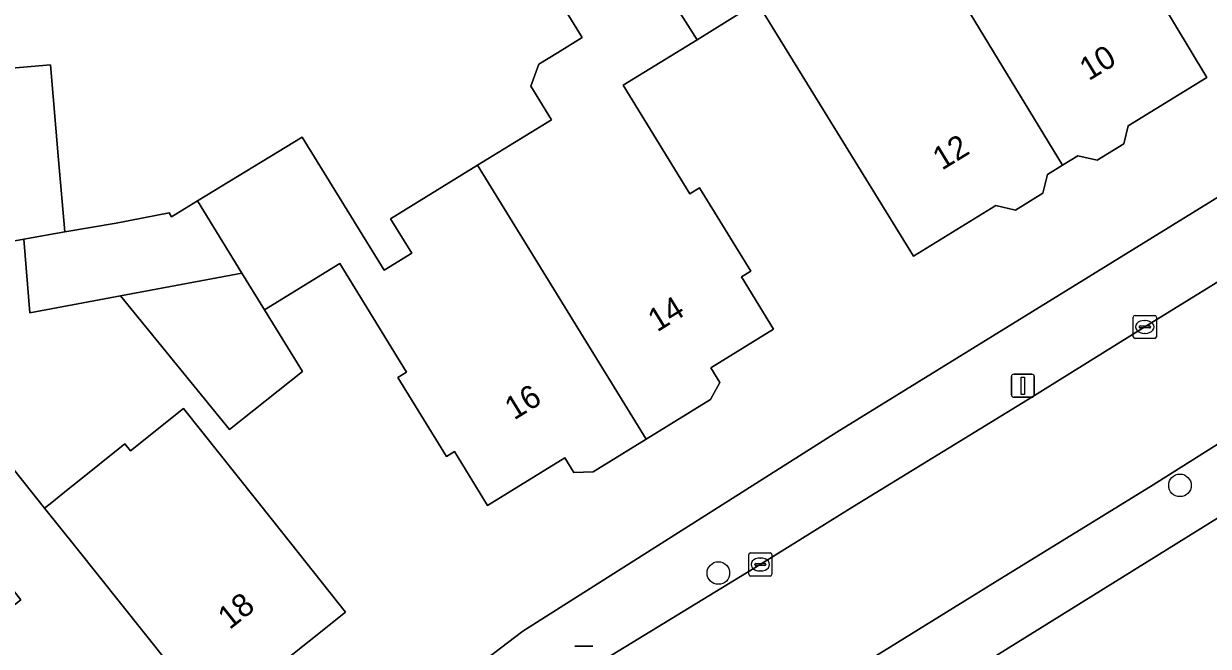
# Model space of a CAD drawing. Extents: x 161347 to 161881, y 382161 to 382804.
# Drawn here: x 161497.7 to 161549.1, y 382335.1 to 382362.1 of the extents above; entities that cross this region are included whole.
import ezdxf

# ---------------------------------------------------------------- set-up
doc = ezdxf.new("R2010")
doc.units = 0
for name, color, linetype in [('IMGEO_Boom', 7, 'Continuous'), ('IMGEO_Erf', 7, 'Continuous'), ('IMGEO_Kolk', 7, 'Continuous'), ('IMGEO_Lichtmast', 7, 'Continuous'), ('IMGEO_Pand', 7, 'Continuous'), ('IMGEO_Pand_nummerreeks', 7, 'Continuous'), ('IMGEO_Rijbaan_lokaal_open', 7, 'Continuous'), ('IMGEO_Voetpad_open', 7, 'Continuous')]:
    doc.layers.add(name, color=color, linetype=linetype)

msp = doc.modelspace()

# ---------------------------------------------------------------- linework, layer by layer
at = {"layer": 'IMGEO_Boom'}
for centre in [(161547.837, 382342.1), (161527.839, 382338.303)]:
    msp.add_circle(centre, 0.489, dxfattribs=at)
at = {"layer": 'IMGEO_Erf'}
for points in [[(161492.761, 382318.284), (161495.67, 382317.265), (161500, 382320.746), (161506.91, 382326.302), (161519.365, 382335.787), (161532.97, 382344.41), (161567.929, 382365.979), (161578.374, 382372.283), (161617.144, 382396.335)], [(161622.482, 382385.769), (161592.982, 382367.466), (161570.924, 382353.999), (161525.486, 382325.795), (161515.87, 382318.353), (161502.943, 382308.001)], [(161541.411, 382372.389), (161548.998, 382359.767), (161545.591, 382357.669), (161545.408, 382356.898), (161544.243, 382356.181), (161543.409, 382356.379), (161542.751, 382355.974), (161542.092, 382355.568), (161541.897, 382354.749), (161540.709, 382354.017), (161539.857, 382354.22), (161536.289, 382352.023), (161529.524, 382363.007), (161526.913, 382361.399), (161523.711, 382359.427), (161526.606, 382354.727), (161527.02, 382354.982), (161529.239, 382351.379), (161528.839, 382351.133), (161530.233, 382348.869), (161527.506, 382347.19), (161527.899, 382346.551), (161527.504, 382345.82), (161524.713, 382344.101), (161522.412, 382342.684), (161521.578, 382342.66), (161521.185, 382343.298), (161517.835, 382341.235), (161516.401, 382343.565), (161516.059, 382343.354), (161513.953, 382346.775), (161514.328, 382347.006), (161511.435, 382351.707), (161508.174, 382349.7), (161509.821, 382347.027), (161506.662, 382344.526), (161501.933, 382350.307), (161498.009, 382349.575), (161497.75, 382352.769), (161497.358, 382352.698)], [(161496.711, 382360.131), (161498.911, 382360.315), (161499.257, 382356.205), (161499.52, 382353.085), (161501.753, 382353.46), (161504.044, 382353.9), (161504.147, 382353.731), (161505.273, 382354.418), (161509.811, 382357.184), (161513.362, 382351.416), (161514.557, 382352.152), (161513.638, 382353.644), (161517.407, 382355.965), (161520.609, 382357.937), (161519.714, 382359.39), (161520.065, 382360.343), (161520.868, 382360.838), (161521.941, 382361.498), (161519.162, 382366.01)]]:
    msp.add_lwpolyline(points, dxfattribs=at)
msp.add_lwpolyline([(161511.691, 382336.608), (161508.532, 382334.091), (161508.385, 382332.789), (161507.808, 382332.33), (161506.507, 382332.477), (161505.918, 382332.008), (161502.662, 382329.412), (161502.518, 382328.135), (161501.894, 382327.638), (161500.663, 382327.777), (161500, 382327.253), (161497.42, 382325.215), (161491.686, 382332.42), (161497.616, 382337.139), (161494.169, 382341.47), (161496.735, 382343.512), (161498.649, 382341.115), (161498.885, 382341.304), (161499.745, 382341.991), (161500, 382342.195), (161502.125, 382343.894), (161502.363, 382343.594), (161504.663, 382345.427), (161508.575, 382340.519)], close=True, dxfattribs=at)
at = {"layer": 'IMGEO_Kolk'}
for p, q in [((161545.89, 382349.463), (161546.742, 382349.463)), ((161545.815, 382348.537), (161545.815, 382349.389)), ((161546.074, 382348.957), (161546.074, 382348.969)), ((161546.512, 382348.92), (161546.114, 382348.92)), ((161546.117, 382349.006), (161546.515, 382349.006)), ((161546.303, 382349.243), (161546.328, 382349.243)), ((161546.558, 382348.969), (161546.558, 382348.957)), ((161546.816, 382349.389), (161546.816, 382348.537)), ((161546.742, 382348.463), (161545.89, 382348.463)), ((161546.326, 382348.683), (161546.301, 382348.683)), ((161529.231, 382339.174), (161530.083, 382339.174)), ((161529.156, 382338.248), (161529.156, 382339.1)), ((161529.415, 382338.668), (161529.415, 382338.68)), ((161529.853, 382338.631), (161529.455, 382338.631)), ((161529.458, 382338.717), (161529.856, 382338.717)), ((161529.644, 382338.954), (161529.669, 382338.954)), ((161529.899, 382338.68), (161529.899, 382338.668)), ((161530.157, 382339.1), (161530.157, 382338.248)), ((161530.083, 382338.174), (161529.231, 382338.174)), ((161529.667, 382338.394), (161529.642, 382338.394))]:
    msp.add_line(p, q, dxfattribs=at)
for points in [[(161545.89, 382349.463), (161546.742, 382349.463)], [(161545.815, 382348.537), (161545.815, 382349.389)], [(161546.816, 382349.389), (161546.816, 382348.537)], [(161546.742, 382348.463), (161545.89, 382348.463)], [(161529.231, 382339.174), (161530.083, 382339.174)], [(161529.156, 382338.248), (161529.156, 382339.1)], [(161530.157, 382339.1), (161530.157, 382338.248)], [(161530.083, 382338.174), (161529.231, 382338.174)]]:
    msp.add_lwpolyline(points, dxfattribs=at)
for centre, radius, start, end in [((161545.892, 382349.387), 0.0765, 91.552, 178.448), ((161545.892, 382349.387), 0.0765, 91.552, 178.448), ((161546.74, 382349.387), 0.0765, 1.552, 88.448), ((161546.74, 382349.387), 0.0765, 1.552, 88.448), ((161546.114, 382348.966), 0.0403, 85.8775, 175.7526), ((161546.111, 382348.956), 0.0366, 178.938, 274.7102), ((161546.515, 382348.963), 0.043, 264.8664, 352.4533), ((161546.519, 382348.968), 0.0386, 1.7309, 96.639), ((161545.892, 382348.539), 0.0765, 181.552, 268.448), ((161545.892, 382348.539), 0.0765, 181.552, 268.448), ((161546.74, 382348.539), 0.0765, 271.552, 358.448), ((161546.74, 382348.539), 0.0765, 271.552, 358.448), ((161529.233, 382339.098), 0.0765, 91.552, 178.448), ((161529.233, 382339.098), 0.0765, 91.552, 178.448), ((161530.081, 382339.098), 0.0765, 1.552, 88.448), ((161530.081, 382339.098), 0.0765, 1.552, 88.448), ((161529.455, 382338.677), 0.0403, 85.8775, 175.7526), ((161529.452, 382338.667), 0.0366, 178.938, 274.7102), ((161529.856, 382338.674), 0.043, 264.8664, 352.4533), ((161529.86, 382338.679), 0.0386, 1.7309, 96.639), ((161529.233, 382338.25), 0.0765, 181.552, 268.448), ((161529.233, 382338.25), 0.0765, 181.552, 268.448), ((161530.081, 382338.25), 0.0765, 271.552, 358.448), ((161530.081, 382338.25), 0.0765, 271.552, 358.448)]:
    msp.add_arc(centre, radius, start, end, dxfattribs=at)
for centre, major_axis, ratio, start_param, end_param in [((161546.302, 382348.963), (-0.387, 0.002), 0.722429, 4.712389, 7.853982), ((161546.327, 382348.963), (-0.39, 0.002), 0.717154, 1.570796, 4.712389), ((161529.643, 382338.674), (-0.387, 0.002), 0.722429, 4.712389, 7.853982), ((161529.668, 382338.674), (-0.39, 0.002), 0.717154, 1.570796, 4.712389)]:
    msp.add_ellipse(centre, major_axis=major_axis, ratio=ratio, start_param=start_param, end_param=end_param, dxfattribs=at)
at = {"layer": 'IMGEO_Lichtmast'}
for p, q in [((161540.634, 382346.916), (161541.424, 382346.916)), ((161541.424, 382346.916), (161540.634, 382346.916)), ((161540.534, 382346.016), (161540.534, 382346.816)), ((161540.534, 382346.816), (161540.534, 382346.016)), ((161541.524, 382346.816), (161541.524, 382346.016)), ((161541.524, 382346.016), (161541.524, 382346.816)), ((161541.424, 382345.916), (161540.634, 382345.916)), ((161540.634, 382345.916), (161541.424, 382345.916)), ((161521.613, 382335.13), (161522.403, 382335.13)), ((161522.403, 382335.13), (161521.613, 382335.13))]:
    msp.add_line(p, q, dxfattribs=at)
msp.add_lwpolyline([(161540.954, 382346.791), (161541.104, 382346.791), (161541.104, 382346.041), (161540.954, 382346.041), (161540.954, 382346.791)], dxfattribs=at)
for centre, start, end in [((161540.634, 382346.816), 90, 180), ((161540.634, 382346.816), 90, 180), ((161541.424, 382346.816), 0, 90), ((161541.424, 382346.816), 360, 90), ((161540.634, 382346.016), 180, 270), ((161540.634, 382346.016), 180, 270), ((161541.424, 382346.016), 270, 0), ((161541.424, 382346.016), 270, 0)]:
    msp.add_arc(centre, 0.1, start, end, dxfattribs=at)
at = {"layer": 'IMGEO_Pand'}
for points in [[(161536.787, 382365.679), (161537.934, 382363.884), (161542.751, 382355.974), (161543.409, 382356.379), (161544.243, 382356.181), (161545.408, 382356.898), (161545.591, 382357.669), (161548.998, 382359.767), (161541.411, 382372.389), (161543.83, 382373.843), (161542.804, 382375.51), (161539.552, 382380.789), (161535.645, 382387.132), (161535.578, 382387.241), (161532.345, 382385.251), (161540.939, 382372.189), (161538.171, 382370.485), (161540.006, 382367.505)], [(161526.913, 382361.399), (161523.396, 382366.941), (161522.21, 382368.807), (161519.162, 382366.01), (161521.941, 382361.498), (161520.868, 382360.838), (161520.065, 382360.343), (161519.714, 382359.39), (161520.609, 382357.937), (161517.407, 382355.965), (161524.713, 382344.101), (161527.504, 382345.82), (161527.899, 382346.551), (161527.506, 382347.19), (161530.233, 382348.869), (161528.839, 382351.133), (161529.239, 382351.379), (161527.02, 382354.982), (161526.606, 382354.727), (161523.711, 382359.427)], [(161536.787, 382365.679), (161533.288, 382363.694), (161531.537, 382366.537), (161528.524, 382364.681), (161526.105, 382368.609), (161523.396, 382366.941), (161526.913, 382361.399), (161529.524, 382363.007), (161536.289, 382352.023), (161539.857, 382354.22), (161540.709, 382354.017), (161541.897, 382354.749), (161542.092, 382355.568), (161542.751, 382355.974), (161537.934, 382363.884)], [(161497.75, 382352.769), (161497.752, 382352.769), (161499.52, 382353.085), (161499.257, 382356.205), (161498.911, 382360.315), (161496.711, 382360.131), (161496.653, 382360.502), (161490.935, 382360.023), (161485.952, 382359.604), (161486.037, 382358.585), (161485.408, 382357.84), (161485.507, 382356.655), (161486.255, 382356.023), (161486.61, 382351.797), (161489.441, 382352.035), (161489.468, 382351.71), (161493.453, 382352.045), (161493.425, 382352.37), (161497.358, 382352.698)], [(161505.273, 382354.418), (161507.196, 382351.29), (161508.174, 382349.7), (161511.435, 382351.707), (161514.328, 382347.006), (161513.953, 382346.775), (161516.059, 382343.354), (161516.401, 382343.565), (161517.835, 382341.235), (161521.185, 382343.298), (161521.578, 382342.66), (161522.412, 382342.684), (161524.713, 382344.101), (161517.407, 382355.965), (161513.638, 382353.644), (161514.557, 382352.152), (161513.362, 382351.416), (161509.811, 382357.184)], [(161505.273, 382354.418), (161504.147, 382353.731), (161504.044, 382353.9), (161501.753, 382353.46), (161499.52, 382353.085), (161497.752, 382352.769), (161497.75, 382352.769), (161498.009, 382349.575), (161501.933, 382350.307), (161507.196, 382351.29)], [(161508.174, 382349.7), (161507.196, 382351.29), (161501.933, 382350.307), (161506.662, 382344.526), (161509.821, 382347.027)], [(161498.649, 382341.115), (161500, 382339.422), (161505.918, 382332.008), (161506.507, 382332.477), (161507.808, 382332.33), (161508.385, 382332.789), (161508.532, 382334.091), (161511.691, 382336.608), (161508.575, 382340.519), (161504.663, 382345.427), (161502.363, 382343.594), (161502.125, 382343.894), (161500, 382342.195), (161499.745, 382341.991), (161498.885, 382341.304)], [(161498.649, 382341.115), (161496.735, 382343.512), (161494.169, 382341.47), (161497.616, 382337.139), (161491.686, 382332.42), (161497.42, 382325.215), (161500, 382327.253), (161500.663, 382327.777), (161501.894, 382327.638), (161502.518, 382328.135), (161502.662, 382329.412), (161505.918, 382332.008), (161500, 382339.422)]]:
    msp.add_lwpolyline(points, close=True, dxfattribs=at)
at = {"layer": 'IMGEO_Rijbaan_lokaal_open'}
msp.add_lwpolyline([(161527.695, 382330.423), (161533.292, 382333.868), (161540.031, 382338.038), (161546.562, 382342.054), (161553.326, 382346.303), (161550.162, 382351.34), (161546.313, 382348.96), (161541.227, 382345.802), (161533.737, 382341.207), (161529.654, 382338.671), (161522.13, 382334.077)], dxfattribs=at)
at = {"layer": 'IMGEO_Voetpad_open'}
for points in [[(161588.821, 382375.192), (161595.489, 382379.316), (161598.349, 382381.063), (161606.195, 382385.906), (161608.544, 382387.356), (161617.711, 382393.014), (161617.891, 382393.131), (161617.144, 382396.335), (161578.374, 382372.283), (161567.929, 382365.979), (161532.97, 382344.41), (161519.365, 382335.787), (161506.91, 382326.302), (161500, 382320.746), (161495.67, 382317.265), (161490.849, 382315.425), (161491.37, 382314.562)], [(161570.924, 382353.999), (161592.982, 382367.466), (161622.482, 382385.769), (161620.875, 382387.995), (161620.649, 382387.867), (161611.66, 382382.307), (161609.313, 382380.856), (161601.422, 382375.975), (161597.335, 382373.472), (161594.082, 382371.461), (161584.84, 382365.72), (161582.402, 382364.234), (161575.759, 382360.113), (161563.07, 382352.279), (161557.478, 382348.912), (161555.662, 382347.771), (161553.326, 382346.303), (161546.562, 382342.054), (161540.031, 382338.038), (161533.292, 382333.868), (161527.695, 382330.423)], [(161522.13, 382334.077), (161529.654, 382338.671), (161533.737, 382341.207), (161541.227, 382345.802), (161546.313, 382348.96), (161550.162, 382351.34), (161552.057, 382352.512), (161552.51, 382352.791), (161558.736, 382356.63), (161563.81, 382359.731), (161570.286, 382363.724), (161577.21, 382368.009), (161581.313, 382370.53), (161588.821, 382375.192)], [(161498.134, 382305.394), (161498.735, 382304.575), (161502.943, 382308.001), (161515.87, 382318.353), (161525.486, 382325.795), (161570.924, 382353.999)]]:
    msp.add_lwpolyline(points, dxfattribs=at)

# ---------------------------------------------------------------- texts
at = {"layer": 'IMGEO_Pand_nummerreeks'}
for s, rotation, p in [('10', 31.3553, (161543.884, 382359.601)), ('12', 31.3553, (161537.524, 382355.726)), ('14', 31.6215, (161525.186, 382348.72)), ('16', 31.6225, (161518.987, 382344.904)), ('18', 38.5486, (161506.662, 382335.823))]:
    msp.add_text(s, height=1, rotation=rotation, dxfattribs=at).set_placement(p)

doc.saveas('drawing.dxf')
